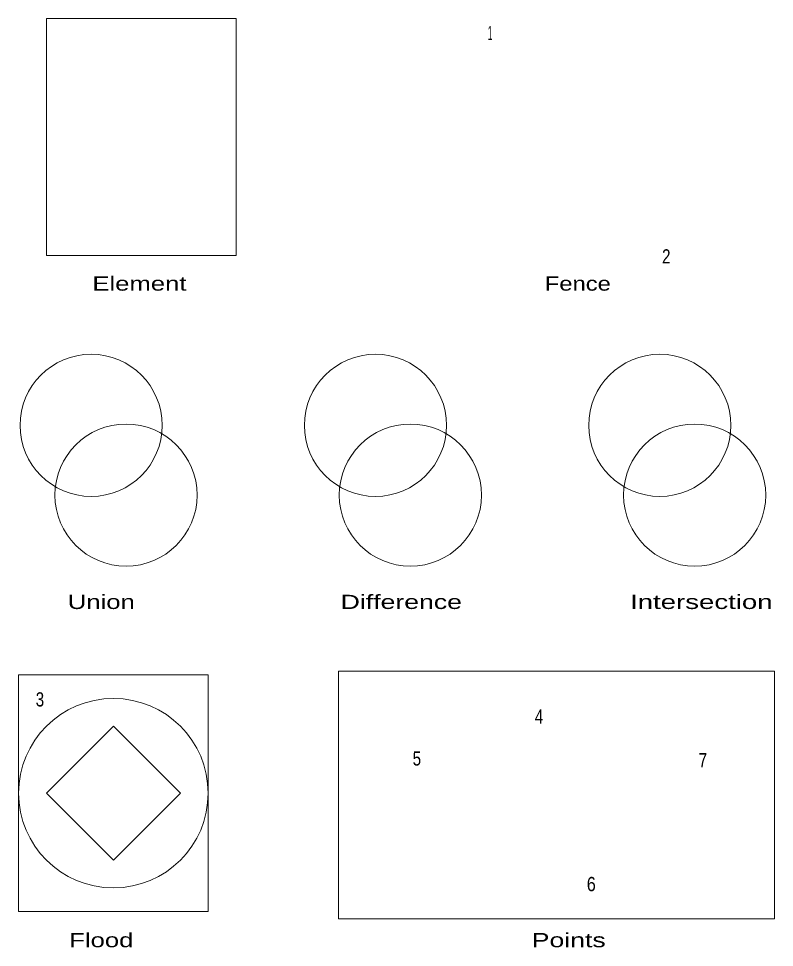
# Model space of a CAD drawing. Extents: x -6.49 to 1.49, y 6.73 to 16.54.
import ezdxf
from ezdxf.enums import TextEntityAlignment as Align

# ---------------------------------------------------------------- set-up
doc = ezdxf.new("R2010")
doc.units = 0
doc.header["$LTSCALE"] = 0.06
doc.layers.add('1', color=7, linetype='Continuous', lineweight=13)

msp = doc.modelspace()

# ---------------------------------------------------------------- linework, layer by layer
at = {"layer": '1'}
for points in [[(-6.1902, 14.039), (-4.1902, 14.039), (-4.1902, 16.539), (-6.1902, 16.539)], [(-6.4851, 7.1127), (-4.4851, 7.1127), (-4.4851, 9.6127), (-6.4851, 9.6127)], [(-3.1108, 9.6502), (1.4898, 9.6502), (1.4898, 7.0353), (-3.1108, 7.0353)], [(-5.4851, 7.6556), (-4.778, 8.3627), (-5.4851, 9.0698), (-6.1922, 8.3627)]]:
    msp.add_lwpolyline(points, close=True, dxfattribs=at)
for centre, radius in [((-5.71941, 12.24536), 0.75), ((-2.71941, 12.24536), 0.75), ((0.28059, 12.24536), 0.75), ((-5.35137, 11.50876), 0.75), ((-2.35137, 11.50876), 0.75), ((0.64863, 11.50876), 0.75), ((-5.48511, 8.36269), 1)]:
    msp.add_circle(centre, radius, dxfattribs=at)

# ---------------------------------------------------------------- texts
for s, width, p in [('1', 0.45, (-1.5097, 16.3114)), ('2', 0.8, (0.34885, 13.9542)), ('Element', 1.35, (-5.21025, 13.6669)), ('Fence', 1.25, (-0.5845, 13.6669)), ('Union', 1.35, (-5.61255, 10.3067)), ('Difference', 1.4, (-2.44705, 10.3067)), ('Intersection', 1.45, (0.71845, 10.3067)), ('3', 0.8, (-6.25965, 9.2776)), ('4', 0.8, (-0.99455, 9.0965)), ('5', 0.8, (-2.2827, 8.6545)), ('7', 0.8, (0.73525, 8.6361)), ('6', 0.85, (-0.44245, 7.3286)), ('Flood', 1.35, (-5.61255, 6.7365)), ('Points', 1.4, (-0.68065, 6.7365))]:
    msp.add_text(s, height=0.15, dxfattribs=dict(at, width=width)).set_placement(p, align=Align.CENTER)

doc.saveas('drawing.dxf')
